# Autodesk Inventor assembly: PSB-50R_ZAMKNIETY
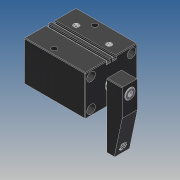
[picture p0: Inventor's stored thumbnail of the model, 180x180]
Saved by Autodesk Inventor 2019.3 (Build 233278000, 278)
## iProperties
Created: 2010-02
Part Number: PSB-50R_ZAMKNIETY
Material: Ogólny
Document SubType Name: Assembly
Designer: CADENGINEERING4
Sending System: PRO/ENGINEER BY PARAMETRIC TECHNOLOGY CORPORATION, 2007170
Preprocessor: PRO/ENGINEER BY PARAMETRIC TECHNOLOGY CORPORATION, 2007170
Title: PSB-50_ASM
Author: Administrator
Revision Number: 1LAST_VERSION
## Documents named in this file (6)
- E:\SERWER_ZAPAS\Pneumatic\PSB PNEUMATIC SWING\PSB-50\PSB-50R_ZAMKNIETY.iam
- E:\SERWER_ZAPAS\Pneumatic\PSB PNEUMATIC SWING\PSB-50\PSB-50BT.ipt
- E:\SERWER_ZAPAS\Pneumatic\PSB PNEUMATIC SWING\PSB-50\PSB-50HSG.ipt
- E:\SERWER_ZAPAS\Pneumatic\PSB PNEUMATIC SWING\PSB-50\PSB-50HG.ipt
- E:\SERWER_ZAPAS\Pneumatic\PSB PNEUMATIC SWING\PSB-50\PSB-50YB.ipt
- E:\SERWER_ZAPAS\Pneumatic\PSB PNEUMATIC SWING\PSB-50\M10LC.ipt
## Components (5 placed, 5 different names)
1. PSB-50BT_0 — Zestawiające:6, Kątowe:1
2. PSB-50HSG_1 — Zestawiające:1, Zestawiające:4, Zestawiające:6, Zestawiające:7
3. PSB-50HG_2 — Zestawiające:7
4. PSB-50YB_3 — Zestawiające:1, Zestawiające:2, Zestawiające:4, Zestawiające:5, Kątowe:1
5. M10LC_4 — Zestawiające:2, Zestawiające:5
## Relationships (7: Mate 6, Angle 1)
- Zestawiające:1 [Mate]: PSB-50HSG_1 ↔ PSB-50YB_3
- Zestawiające:2 [Mate]: PSB-50YB_3 ↔ M10LC_4
- Zestawiające:4 [Mate]: PSB-50HSG_1 ↔ PSB-50YB_3
- Zestawiające:5 [Mate]: PSB-50YB_3 ↔ M10LC_4
- Zestawiające:6 [Mate]: PSB-50BT_0 ↔ PSB-50HSG_1
- Zestawiające:7 [Mate]: PSB-50HSG_1 ↔ PSB-50HG_2
- Kątowe:1 [Angle]: PSB-50BT_0 ↔ PSB-50YB_3
